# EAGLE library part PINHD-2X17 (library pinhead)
PIN HEADER
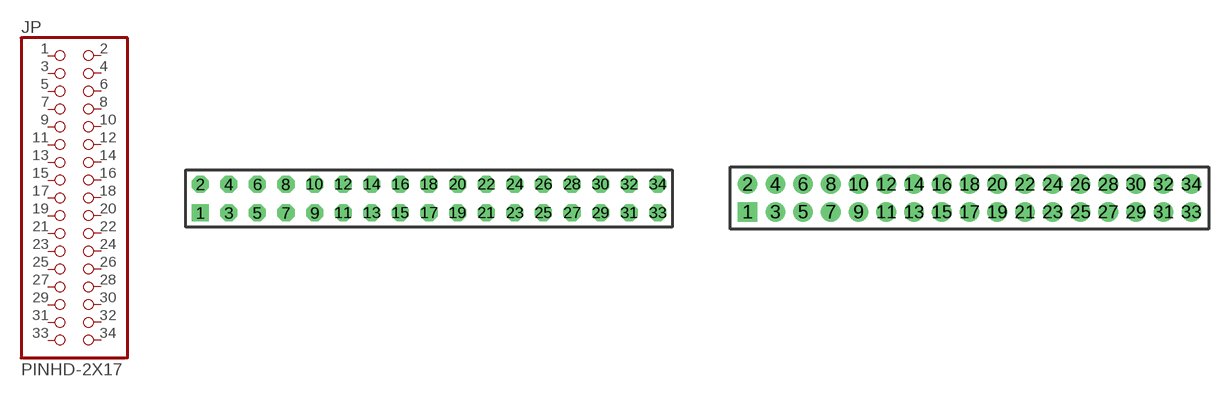
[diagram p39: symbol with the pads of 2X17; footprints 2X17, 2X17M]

Designator prefix JP

## PINHD-2X17  [2X17]
1  1  pas
2  2  pas
3  3  pas
4  4  pas
5  5  pas
6  6  pas
7  7  pas
8  8  pas
9  9  pas
10  10  pas
11  11  pas
12  12  pas
13  13  pas
14  14  pas
15  15  pas
16  16  pas
17  17  pas
18  18  pas
19  19  pas
20  20  pas
21  21  pas
22  22  pas
23  23  pas
24  24  pas
25  25  pas
26  26  pas
27  27  pas
28  28  pas
29  29  pas
30  30  pas
31  31  pas
32  32  pas
33  33  pas
34  34  pas

## PINHD-2X17M  [2X17M]
Pads as for 2X17

## Footprint 2X17 (pad centres in mm)
PIN HEADER - 0.1"
drill 1.016 square: 1 -20.32,-1.27
drill 1.016 octagon: 2 -20.32,1.27; 3 -17.78,-1.27; 4 -17.78,1.27; 5 -15.24,-1.27; 6 -15.24,1.27; 7 -12.7,-1.27; 8 -12.7,1.27; 9 -10.16,-1.27; 10 -10.16,1.27; 11 -7.62,-1.27; 12 -7.62,1.27; 13 -5.08,-1.27; 14 -5.08,1.27; 15 -2.54,-1.27; 16 -2.54,1.27; 17 0,-1.27; 18 0,1.27; 19 2.54,-1.27; 20 2.54,1.27; 21 5.08,-1.27; 22 5.08,1.27; 23 7.62,-1.27; 24 7.62,1.27; 25 10.16,-1.27; 26 10.16,1.27; 27 12.7,-1.27; 28 12.7,1.27; 29 15.24,-1.27; 30 15.24,1.27; 31 17.78,-1.27; 32 17.78,1.27; 33 20.32,-1.27; 34 20.32,1.27

## Footprint 2X17M (pad centres in mm)
PIN HEADER - 2MM"
drill 0.914 square: 1 -16,-1
drill 0.914 round: 2 -16,1; 3 -14,-1; 4 -14,1; 5 -12,-1; 6 -12,1; 7 -10,-1; 8 -10,1; 9 -8,-1; 10 -8,1; 11 -6,-1; 12 -6,1; 13 -4,-1; 14 -4,1; 15 -2,-1; 16 -2,1; 17 0,-1; 18 0,1; 19 2,-1; 20 2,1; 21 4,-1; 22 4,1; 23 6,-1; 24 6,1; 25 8,-1; 26 8,1; 27 10,-1; 28 10,1; 29 12,-1; 30 12,1; 31 14,-1; 32 14,1; 33 16,-1; 34 16,1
